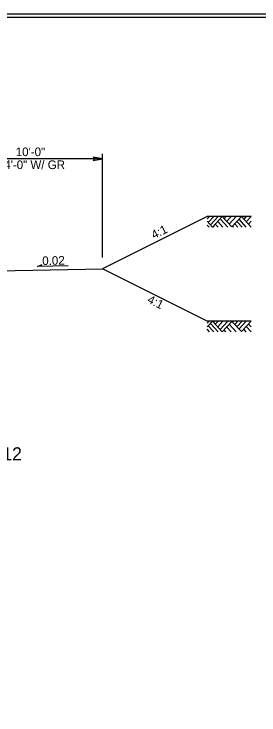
# Model space of a CAD drawing. Extents: x 1901670 to 1902225, y 193498 to 194278.
# Drawn here: x 1902044.9 to 1902063.5, y 193552.5 to 193605.8 of the extents above; entities that cross this region are included whole.
import ezdxf

# ---------------------------------------------------------------- set-up
doc = ezdxf.new("R2010")
doc.units = 0
for name, color, linetype in [('Old_Level_1', 7, 'Continuous'), ('Old_Level_11', 7, 'Continuous'), ('Old_Level_2', 7, 'Continuous'), ('Prop Dimension', 7, 'Continuous'), ('Sheet Border Standard 30in CELL', 7, 'Continuous'), ('Sheet Plot Border Inside CELL', 7, 'Continuous'), ('Typical Pavement Slope CELL', 7, 'Continuous'), ('Typical Terminator CELL', 7, 'Continuous')]:
    doc.layers.add(name, color=color, linetype=linetype)

# ---------------------------------------------------------------- blocks, each defined once
blk = doc.blocks.new('TERMINATOR')
at = {"layer": 'Typical Terminator CELL'}
blk.add_lwpolyline([(-0.469, 0.081), (0, 0), (-0.471, -0.083), (-0.411, 0)], close=True, dxfattribs=at)

msp = doc.modelspace()

# ---------------------------------------------------------------- linework, layer by layer
at = {"layer": 'Old_Level_1'}
for p, q in [((1902059.748, 193590.366), (1902059.578, 193590.183)), ((1902060.068, 193590.366), (1902059.654, 193589.922)), ((1902060.401, 193590.366), (1902059.821, 193589.743)), ((1902060.723, 193590.365), (1902059.982, 193589.569)), ((1902061.454, 193589.579), (1902060.723, 193590.365)), ((1902060.987, 193590.366), (1902060.854, 193590.223)), ((1902061.389, 193590.366), (1902061.056, 193590.007)), ((1902061.787, 193590.366), (1902061.254, 193589.793)), ((1902062.178, 193590.358), (1902061.454, 193589.579)), ((1902062.92, 193589.561), (1902062.178, 193590.358)), ((1902062.545, 193590.366), (1902062.358, 193590.165)), ((1902062.92, 193590.366), (1902062.545, 193589.963)), ((1902059.982, 193589.569), (1902059.578, 193590.004)), ((1902060.408, 193589.561), (1902060.191, 193589.794)), ((1902060.774, 193589.561), (1902060.374, 193589.99)), ((1902061.144, 193589.561), (1902060.558, 193590.189)), ((1902061.89, 193589.561), (1902061.663, 193589.804)), ((1902062.237, 193589.561), (1902061.836, 193589.99)), ((1902062.546, 193589.561), (1902061.992, 193590.157)), ((1902062.92, 193590.004), (1902062.714, 193589.782)), ((1902059.712, 193589.561), (1902059.578, 193589.704)), ((1902060.113, 193589.561), (1902060.044, 193589.635)), ((1902061.579, 193589.561), (1902061.508, 193589.637)), ((1902046.691, 193586.558), (1902047.024, 193586.725)), ((1902049.006, 193586.607), (1902046.691, 193586.558)), ((1902059.712, 193582.409), (1902059.578, 193582.266)), ((1902059.982, 193582.401), (1902059.578, 193581.966)), ((1902060.723, 193581.605), (1902059.982, 193582.401)), ((1902060.113, 193582.409), (1902060.044, 193582.335)), ((1902060.408, 193582.409), (1902060.191, 193582.176)), ((1902060.774, 193582.409), (1902060.374, 193581.98)), ((1902061.144, 193582.409), (1902060.558, 193581.781)), ((1902061.454, 193582.391), (1902060.723, 193581.605)), ((1902062.178, 193581.612), (1902061.454, 193582.391)), ((1902061.579, 193582.409), (1902061.508, 193582.333)), ((1902061.89, 193582.409), (1902061.663, 193582.166)), ((1902062.237, 193582.409), (1902061.836, 193581.98)), ((1902062.546, 193582.409), (1902061.992, 193581.813)), ((1902062.92, 193582.409), (1902062.178, 193581.612)), ((1902059.748, 193581.604), (1902059.578, 193581.787)), ((1902060.068, 193581.604), (1902059.654, 193582.048)), ((1902060.401, 193581.604), (1902059.821, 193582.227)), ((1902060.987, 193581.604), (1902060.854, 193581.747)), ((1902061.389, 193581.604), (1902061.056, 193581.963)), ((1902061.787, 193581.604), (1902061.254, 193582.177)), ((1902062.545, 193581.604), (1902062.358, 193581.805)), ((1902062.92, 193581.604), (1902062.545, 193582.007)), ((1902062.92, 193581.966), (1902062.714, 193582.188))]:
    msp.add_line(p, q, dxfattribs=at)
at = {"layer": 'Prop Dimension'}
for p, q in [((1902051.621, 193587.249), (1902051.621, 193595.131)), ((1902051.621, 193594.761), (1902041.621, 193594.761))]:
    msp.add_line(p, q, dxfattribs=at)
at = {"layer": 'Sheet Border Standard 30in CELL'}
msp.add_lwpolyline([(1902132.544, 193605.514), (1901982.544, 193605.514), (1901982.544, 193500.514), (1902132.544, 193500.514)], close=True, dxfattribs=at)
at = {"layer": 'Sheet Plot Border Inside CELL'}
msp.add_lwpolyline([(1902133.794, 193605.769), (1901967.144, 193605.769), (1901967.144, 193500.259), (1902133.794, 193500.259)], close=True, dxfattribs=at)
at = {"layer": 'Typical Pavement Slope CELL'}
for p in [(1902059.578, 193590.366), (1902042.12, 193586.198), (1902059.578, 193582.409)]:
    msp.add_line(p, (1902051.621, 193586.388), dxfattribs=at)
for points in [[(1902062.92, 193590.366), (1902059.578, 193590.366)], [(1902062.92, 193582.409), (1902059.578, 193582.409)]]:
    msp.add_lwpolyline(points, dxfattribs=at)

# ---------------------------------------------------------------- block references
at = {"layer": 'Prop Dimension', "xscale": 1.5, "yscale": -1.5}
msp.add_blockref('TERMINATOR', (1902051.621, 193594.761), dxfattribs=at)

# ---------------------------------------------------------------- texts
at = {"layer": 'Old_Level_1'}
for rotation, p in [(26.5651, (1902055.531, 193588.633)), (333.4349, (1902054.965, 193583.842))]:
    msp.add_text('4:1', height=0.656, rotation=rotation, dxfattribs=at).set_placement(p)
at = {"layer": 'Old_Level_11'}
msp.add_text('TRANSITION FROM EXISTING TO TYPICAL SECTION NO. 12', height=1, dxfattribs=at).set_placement((1902007.378, 193571.814))
at = {"layer": 'Old_Level_2'}
msp.add_text('0.02', height=0.656, rotation=1.1916, dxfattribs=at).set_placement((1902047.047, 193586.677))
at = {"layer": 'Prop Dimension'}
for s, p in [('10\'-0" ', (1902045.025, 193594.959)), ('14\'-0" W/ GR ', (1902043.663, 193593.976))]:
    msp.add_text(s, height=0.656, dxfattribs=at).set_placement(p)

doc.saveas('drawing.dxf')
